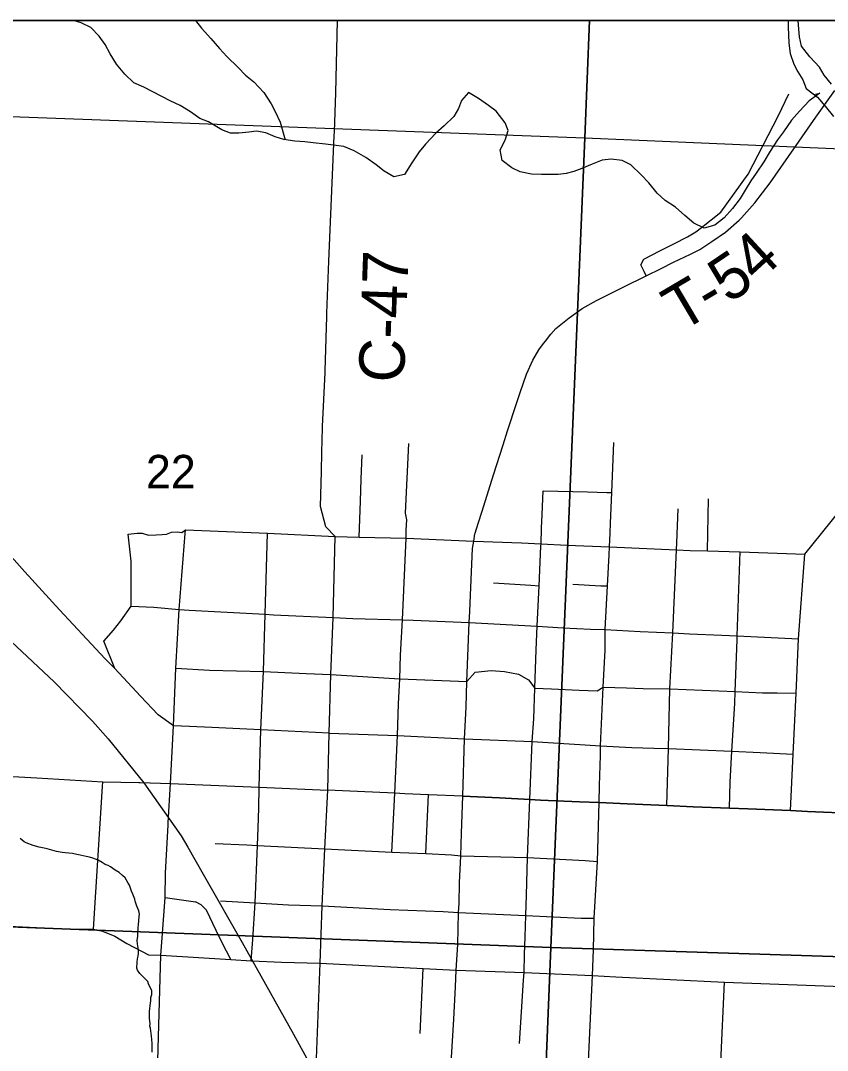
# Model space of a CAD drawing. Extents: x 0 to 34, y 0 to 22.
# Drawn here: x 3.4 to 4.408, y 19.613 to 20.9 of the extents above; entities that cross this region are included whole.
import ezdxf

# ---------------------------------------------------------------- set-up
doc = ezdxf.new("R2010")
doc.units = 0
for name, color, linetype in [('Default', 7, 'Continuous'), ('GM_X_City_Street', 7, 'Continuous'), ('GM_X_County_Road', 7, 'Continuous'), ('GM_X_County_Road_Text', 7, 'Continuous'), ('GM_X_Major_River', 7, 'Continuous'), ('GM_X_Minor_River', 7, 'Continuous'), ('GM_X_Rail_Line', 7, 'Continuous'), ('GM_X_Section', 7, 'Continuous'), ('GM_X_Section_Text', 7, 'Continuous'), ('GM_X_State_Route', 7, 'Continuous'), ('GM_X_Township_Road', 7, 'Continuous'), ('GM_X_Township_Road_Text', 7, 'Continuous'), ('GM_X_US_Route', 7, 'Continuous'), ('SH_Data', 7, 'Continuous')]:
    doc.layers.add(name, color=color, linetype=linetype)

msp = doc.modelspace()

# ---------------------------------------------------------------- linework, layer by layer
at = {"layer": 'Default'}
msp.add_lwpolyline([(6.0871, 20.9), (2.1, 20.9), (2.1, 17.8044), (2.8305, 17.7727), (2.976, 17.7664), (3.1037, 17.7609), (3.4544, 17.7458), (3.7662, 17.7368), (3.9904, 17.7296), (4.1165, 17.7286), (4.1238, 17.7269), (4.1354, 17.7264), (4.1969, 17.7246), (4.2769, 17.7222), (4.4203, 17.718), (4.506, 17.7155), (4.6237, 17.7121), (4.6735, 17.7102), (4.763, 17.7084), (4.9045, 17.7039), (4.98, 17.7015), (5.0396, 17.6997)], dxfattribs=at)
for points in [[(4.1106, 20.9), (3.1115, 20.9), (3.1076, 20.7906), (4.105, 20.7535)], [(5.1123, 20.9), (4.1106, 20.9), (4.105, 20.7535), (5.1049, 20.7104)]]:
    msp.add_lwpolyline(points, close=True, dxfattribs=at)
at = {"layer": 'GM_X_City_Street'}
for p, q in [((4.2579, 20.2373), (4.2594, 20.3024)), ((4.2196, 20.2471), (4.2216, 20.2897)), ((3.5806, 19.8039), (3.6183, 19.7988)), ((3.899, 19.6342), (3.9027, 19.7153)), ((4.0233, 19.6217), (4.0283, 19.7005))]:
    msp.add_line(p, q, dxfattribs=at)
for points in [[(3.8818, 20.2615), (3.8818, 20.2633), (3.8825, 20.276), (3.881, 20.2842), (3.8849, 20.3715)], [(4.1357, 20.2423), (4.1365, 20.2594), (4.137, 20.2717), (4.1385, 20.31), (4.1411, 20.3727)], [(3.8229, 20.2544), (3.8244, 20.2992), (3.8254, 20.327), (3.8268, 20.3574)], [(4.05, 20.2434), (4.0502, 20.2462), (4.0506, 20.2658), (4.0516, 20.2825), (4.0527, 20.3123)], [(4.0527, 20.3123), (4.1082, 20.3109), (4.1323, 20.31), (4.1385, 20.31)], [(3.5343, 20.2582), (3.5454, 20.2592), (3.5517, 20.2592), (3.5597, 20.257), (3.5692, 20.2571), (3.577, 20.2578), (3.5822, 20.2583), (3.5884, 20.2607), (3.5957, 20.2612), (3.6014, 20.2601), (3.6059, 20.2637)], [(3.5382, 20.1681), (3.5381, 20.2242), (3.5343, 20.2582)], [(3.5908, 20.0186), (3.594, 20.0907), (3.598, 20.1638), (3.6055, 20.2589), (3.6059, 20.2637)], [(3.6059, 20.2637), (3.7086, 20.2594), (3.7929, 20.2551), (3.8229, 20.2544), (3.8816, 20.2529), (3.9661, 20.2492)], [(3.6981, 19.9419), (3.7001, 20.0135), (3.7032, 20.0864), (3.7053, 20.1582), (3.7086, 20.2594)], [(3.8706, 20.0064), (3.8722, 20.0461), (3.8737, 20.0774), (3.8744, 20.107), (3.8772, 20.151), (3.8816, 20.2529), (3.8818, 20.2615)], [(3.9661, 20.2492), (4.0257, 20.2471), (4.0502, 20.2462), (4.0823, 20.2445), (4.1357, 20.2423), (4.2192, 20.2385), (4.2364, 20.2376), (4.2579, 20.2373), (4.2989, 20.236), (4.3798, 20.2329)], [(4.2074, 19.9191), (4.2093, 19.9904), (4.2112, 20.065), (4.2149, 20.1349), (4.2192, 20.2385), (4.2196, 20.2471)], [(4.0391, 19.9989), (4.0413, 20.0271), (4.0424, 20.0656), (4.044, 20.1137), (4.0452, 20.1432), (4.0479, 20.1934), (4.0494, 20.2329), (4.05, 20.2434)], [(4.1228, 19.9229), (4.1231, 19.9438), (4.1246, 19.9816), (4.1246, 19.9935), (4.1279, 20.067), (4.1301, 20.1131), (4.1303, 20.1391), (4.1332, 20.1934), (4.1353, 20.2321), (4.1357, 20.2423)], [(4.2855, 19.9157), (4.2866, 19.9483), (4.2884, 19.9869), (4.2922, 20.0465), (4.2926, 20.0614), (4.295, 20.1259), (4.2952, 20.1311), (4.2989, 20.236)], [(4.3619, 19.9126), (4.3652, 19.9832), (4.3688, 20.0595), (4.3719, 20.1273), (4.3798, 20.2329)], [(3.9908, 20.1971), (4.0375, 20.1945), (4.0479, 20.1934)], [(4.0897, 20.1955), (4.125, 20.1937), (4.1332, 20.1934)], [(3.5175, 20.0904), (3.5039, 20.1243), (3.5162, 20.138), (3.5252, 20.1497), (3.5382, 20.1681), (3.5663, 20.1667), (3.598, 20.1638), (3.6107, 20.1632), (3.7053, 20.1582), (3.7158, 20.1574), (3.7904, 20.1539), (3.8151, 20.1526), (3.8772, 20.151), (3.8905, 20.1505), (3.9604, 20.1476)], [(3.9604, 20.1476), (4.0452, 20.1432), (4.0777, 20.1411), (4.1118, 20.1394), (4.1303, 20.1391), (4.174, 20.1365), (4.2149, 20.1349), (4.2355, 20.1335), (4.2759, 20.1319), (4.2952, 20.1311), (4.3719, 20.1273)], [(3.594, 20.0907), (3.6358, 20.0883), (3.7032, 20.0864), (3.7565, 20.084), (3.7876, 20.0826), (3.8737, 20.0774), (3.9574, 20.0739)], [(3.9574, 20.0739), (3.9679, 20.0858), (3.9877, 20.0876), (4.0045, 20.0863), (4.0221, 20.0831), (4.0344, 20.0762), (4.0424, 20.0656), (4.0631, 20.0649), (4.0976, 20.063), (4.1202, 20.0624), (4.1279, 20.067), (4.1568, 20.066), (4.1777, 20.0653), (4.2112, 20.065), (4.2926, 20.0614), (4.3268, 20.06), (4.345, 20.0597), (4.3688, 20.0595)], [(4.0391, 19.9989), (4.1051, 19.9949), (4.1246, 19.9935), (4.1635, 19.9914), (4.1912, 19.9908), (4.2093, 19.9904), (4.2884, 19.9869), (4.3239, 19.9852), (4.3652, 19.9832)], [(3.491, 19.7643), (3.5024, 19.9426), (3.5026, 19.9485)], [(3.6881, 19.7247), (3.6899, 19.7515), (3.693, 19.7973), (3.6958, 19.8691), (3.6966, 19.8911), (3.6974, 19.9155), (3.6981, 19.9419)], [(3.9062, 19.8588), (3.9067, 19.8685), (3.9094, 19.9325)], [(4.1143, 19.7066), (4.1155, 19.7388), (4.1165, 19.778), (4.1208, 19.8492), (4.1228, 19.9229)], [(3.6431, 19.8714), (3.6824, 19.8699), (3.6958, 19.8691), (3.7801, 19.8649)], [(4.0283, 19.7005), (4.0289, 19.7104), (4.0296, 19.7329), (4.0302, 19.755), (4.0311, 19.7815), (4.0318, 19.8068), (4.0333, 19.854)], [(4.0333, 19.854), (4.1054, 19.8501), (4.1208, 19.8492)], [(3.6627, 19.7266), (3.6519, 19.7473), (3.6443, 19.7628), (3.6323, 19.7881), (3.6255, 19.7949), (3.6183, 19.7988)], [(3.6496, 19.7999), (3.693, 19.7973), (3.7347, 19.7947), (3.7767, 19.7936), (3.8618, 19.7891), (3.9277, 19.7865), (3.947, 19.7851)], [(3.947, 19.7851), (4.0311, 19.7815), (4.1004, 19.7781), (4.1165, 19.778)], [(3.5646, 19.1798), (3.5556, 19.2005), (3.5545, 19.2251), (3.5555, 19.2612), (3.5684, 19.4983), (3.5753, 19.7319)], [(4.0935, 19.2396), (4.0939, 19.2473), (4.0951, 19.2853), (4.095, 19.2916), (4.096, 19.3033), (4.0968, 19.3257), (4.0979, 19.3464), (4.0988, 19.3586), (4.0991, 19.3677), (4.099, 19.3763), (4.1143, 19.7066)], [(4.2554, 19.2326), (4.2569, 19.2528), (4.2701, 19.4982), (4.2795, 19.6982)]]:
    msp.add_lwpolyline(points, dxfattribs=at)
at = {"layer": 'GM_X_County_Road'}
for p, q in [((3.7762, 20.3606), (3.7772, 20.3906)), ((3.5753, 19.7319), (3.5769, 19.7535))]:
    msp.add_line(p, q, dxfattribs=at)
for points in [[(3.792, 20.7611), (3.7936, 20.8097), (3.7959, 20.9)], [(3.7825, 20.5302), (3.7826, 20.5342), (3.7851, 20.5995), (3.7918, 20.756), (3.792, 20.7611)], [(3.7803, 20.4601), (3.7804, 20.4621), (3.7825, 20.5302)], [(3.7772, 20.3906), (3.7773, 20.3926), (3.7803, 20.4601)], [(3.7929, 20.2551), (3.7814, 20.2673), (3.7748, 20.2926), (3.776, 20.3363), (3.7762, 20.3606)], [(3.7856, 20.0094), (3.7876, 20.0826), (3.7904, 20.1539), (3.7929, 20.2551)], [(2.7032, 20.1317), (2.7688, 20.0887), (2.8505, 20.0351), (2.9032, 20.0007), (2.921, 19.9928), (2.9306, 19.9898), (2.9591, 19.9866), (3.0508, 19.9729), (3.1096, 19.9678), (3.2187, 19.9627), (3.3527, 19.9573), (3.4202, 19.9534), (3.5026, 19.9485), (3.5475, 19.9479)], [(3.5843, 19.8948), (3.5844, 19.8974), (3.5871, 19.9465), (3.5908, 20.0186)], [(3.7856, 20.0094), (3.8706, 20.0064), (3.9545, 20.0022), (4.0391, 19.9989)], [(3.8637, 19.8607), (3.8675, 19.9343), (3.8706, 20.0064)], [(4.0333, 19.854), (4.0361, 19.9264), (4.0391, 19.9989)], [(3.5475, 19.9479), (3.5495, 19.9479), (3.5871, 19.9465)], [(3.5871, 19.9465), (3.6981, 19.9419), (3.7836, 19.9381)], [(3.774, 19.7218), (3.7767, 19.7936), (3.7801, 19.8649), (3.7836, 19.9381)], [(3.5769, 19.7535), (3.5806, 19.8039), (3.581, 19.8344), (3.5843, 19.8948)], [(3.7801, 19.8649), (3.8637, 19.8607), (3.9062, 19.8588), (3.9381, 19.8572), (3.95, 19.8562), (4.0333, 19.854)], [(2.7427, 19.7956), (2.8581, 19.789), (2.9159, 19.7881), (3.031, 19.7839), (3.2427, 19.773), (3.3579, 19.7693), (3.4112, 19.7668), (3.4626, 19.7644), (3.491, 19.7643), (3.5023, 19.762), (3.5178, 19.7556), (3.5325, 19.7466), (3.5599, 19.7323), (3.5753, 19.7319)], [(3.5753, 19.7319), (3.6627, 19.7266), (3.6881, 19.7247), (3.689, 19.7247)], [(3.689, 19.7247), (3.7258, 19.7231), (3.774, 19.7218), (3.9027, 19.7153), (3.9443, 19.7132)], [(3.7571, 19.254), (3.7606, 19.3413), (3.761, 19.3744), (3.7612, 19.3861), (3.774, 19.7218)], [(3.9443, 19.7132), (4.0289, 19.7104), (4.1143, 19.7066), (4.1437, 19.7048), (4.2795, 19.6982), (4.4492, 19.6919), (4.4711, 19.6913), (4.5591, 19.6887), (4.5735, 19.6877)]]:
    msp.add_lwpolyline(points, dxfattribs=at)
at = {"layer": 'GM_X_Major_River'}
for points in [[(4.3589, 20.9), (4.3587, 20.8916), (4.3592, 20.8821), (4.3596, 20.8719), (4.3612, 20.8589), (4.3661, 20.8455), (4.3708, 20.8359), (4.3773, 20.8258), (4.3812, 20.8151), (4.3957, 20.8041), (4.4049, 20.7932), (4.4155, 20.78)], [(4.4132, 20.8203), (4.4037, 20.8319), (4.3979, 20.8416), (4.3861, 20.8548), (4.3755, 20.868), (4.3731, 20.8795), (4.3723, 20.8894), (4.3715, 20.9)]]:
    msp.add_lwpolyline(points, dxfattribs=at)
at = {"layer": 'GM_X_Minor_River'}
for points in [[(3.5867, 20.7998), (3.5538, 20.8166), (3.5414, 20.8223), (3.5303, 20.8328), (3.5197, 20.8456), (3.512, 20.8583), (3.5055, 20.8702), (3.4982, 20.8806), (3.4875, 20.8915), (3.4755, 20.8971), (3.4659, 20.9)], [(3.6183, 20.9), (3.6261, 20.8906), (3.6375, 20.8774), (3.6486, 20.8649), (3.6574, 20.8552), (3.6718, 20.8415), (3.6811, 20.8318), (3.6915, 20.8235), (3.704, 20.8102), (3.7131, 20.7959), (3.7178, 20.7863), (3.7242, 20.7732), (3.7306, 20.7511)], [(4.3911, 20.8076), (4.3985, 20.8093), (4.3853, 20.7998), (4.3732, 20.7868), (4.363, 20.7757), (4.3531, 20.7608), (4.3456, 20.7508), (4.3365, 20.7366), (4.3285, 20.7235), (4.319, 20.7094), (4.3123, 20.6997), (4.3063, 20.69), (4.2987, 20.6777), (4.2893, 20.665), (4.2791, 20.6535), (4.2671, 20.6444), (4.254, 20.6406), (4.2409, 20.6466), (4.2298, 20.6564), (4.2183, 20.6666), (4.2053, 20.6753), (4.1953, 20.6843), (4.185, 20.6971), (4.1754, 20.7073), (4.1625, 20.7198), (4.1516, 20.725), (4.1376, 20.7269), (4.1266, 20.7257), (4.1139, 20.7207), (4.1012, 20.715), (4.0912, 20.7115), (4.0816, 20.7087), (4.0717, 20.7075), (4.0611, 20.7078), (4.0505, 20.7077), (4.0383, 20.708), (4.024, 20.7111), (4.0135, 20.7159), (4.0016, 20.725), (3.9989, 20.7383), (4.0054, 20.7507), (4.0091, 20.7627), (4.0052, 20.7723), (3.9942, 20.7867), (3.9845, 20.7938), (3.9719, 20.8028), (3.9595, 20.81), (3.9509, 20.8), (3.9472, 20.7902), (3.9412, 20.7802), (3.9291, 20.7683), (3.9186, 20.7591), (3.9057, 20.7455), (3.8979, 20.7358), (3.8887, 20.722), (3.8796, 20.7078), (3.8662, 20.7048), (3.8543, 20.7119), (3.8442, 20.7198), (3.8312, 20.7289), (3.8166, 20.7373), (3.8039, 20.7426), (3.791, 20.7441), (3.7808, 20.7455), (3.7653, 20.7471), (3.755, 20.7485), (3.7425, 20.7492), (3.7286, 20.7515), (3.718, 20.7548), (3.7064, 20.7597), (3.6947, 20.7619), (3.6851, 20.7607), (3.6726, 20.7591), (3.6623, 20.7594), (3.6514, 20.7635), (3.6346, 20.7734), (3.6237, 20.7775), (3.6122, 20.7858), (3.5991, 20.7938), (3.5867, 20.7998)], [(3.5626, 19.6749), (3.5628, 19.679), (3.5637, 19.6828), (3.5638, 19.6874), (3.5628, 19.6901), (3.561, 19.6932), (3.5599, 19.6963), (3.5589, 19.699), (3.5519, 19.7061), (3.5489, 19.7092), (3.546, 19.7131), (3.5453, 19.7158), (3.5456, 19.7231), (3.5461, 19.7272), (3.547, 19.7306), (3.5471, 19.7344), (3.5472, 19.7386), (3.5469, 19.7413), (3.546, 19.7459), (3.5457, 19.7501), (3.5463, 19.7558), (3.5464, 19.7588), (3.547, 19.7664), (3.5471, 19.7699), (3.5482, 19.7801), (3.5483, 19.7832), (3.5477, 19.7874), (3.5452, 19.7932), (3.5432, 19.7993), (3.5425, 19.802), (3.54, 19.8082), (3.5386, 19.8121), (3.5358, 19.8194), (3.5344, 19.8221), (3.5304, 19.8284), (3.5271, 19.8315), (3.523, 19.8351), (3.5181, 19.8383), (3.5122, 19.8423), (3.5092, 19.8439), (3.5058, 19.8452), (3.5017, 19.8476), (3.4968, 19.8505), (3.49, 19.853), (3.4859, 19.8543), (3.4817, 19.8552), (3.4745, 19.8569), (3.47, 19.8579), (3.4647, 19.8588), (3.4555, 19.8599), (3.4517, 19.8604), (3.4449, 19.8614), (3.4332, 19.8648), (3.4294, 19.8657), (3.423, 19.8671), (3.4158, 19.8689), (3.4071, 19.8722), (3.4045, 19.8735), (3.3993, 19.8778)], [(3.5643, 19.6108), (3.5645, 19.615), (3.5642, 19.6184), (3.5643, 19.6215), (3.5637, 19.6264), (3.5635, 19.6306), (3.5632, 19.6341), (3.5623, 19.6406), (3.5616, 19.6433), (3.5617, 19.6463), (3.5608, 19.6532), (3.5611, 19.662), (3.5616, 19.665), (3.5617, 19.6692), (3.5626, 19.6749)]]:
    msp.add_lwpolyline(points, dxfattribs=at)
at = {"layer": 'GM_X_Rail_Line'}
msp.add_lwpolyline([(2.5538, 20.9), (2.6699, 20.7921), (2.9476, 20.533), (3.1327, 20.3614), (3.2237, 20.277), (3.3405, 20.1683), (3.4419, 20.0737), (3.4898, 20.0243), (3.5092, 20.0023), (3.5538, 19.9473), (3.6006, 19.8809), (3.6088, 19.8671), (3.6176, 19.8515), (3.6298, 19.8303), (3.6768, 19.7476), (3.7408, 19.633), (3.7622, 19.5944), (3.79, 19.5454), (4.1053, 18.9832), (4.1141, 18.9644), (4.1259, 18.9412), (4.1333, 18.9272), (4.1473, 18.9034)], dxfattribs=at)
at = {"layer": 'GM_X_Section'}
for points in [[(3.1076, 20.7906), (4.105, 20.7535), (4.0623, 19.7415), (3.0692, 19.7796)], [(5.1049, 20.7104), (5.0674, 19.7096), (4.0623, 19.7415), (4.105, 20.7535)], [(3.0692, 19.7796), (4.0623, 19.7415), (4.0218, 18.7461), (3.0273, 18.7832)], [(4.0623, 19.7415), (5.0674, 19.7096), (5.0264, 18.7096), (4.0218, 18.7461)]]:
    msp.add_lwpolyline(points, close=True, dxfattribs=at)
at = {"layer": 'GM_X_State_Route'}
for points in [[(4.3005, 20.6534), (4.3174, 20.6721), (4.3362, 20.6971), (4.366, 20.7398), (4.3933, 20.7793), (4.4172, 20.8125)], [(4.0532, 20.4963), (4.0555, 20.4994), (4.0622, 20.5081), (4.0688, 20.5151), (4.0853, 20.5286), (4.1013, 20.5401), (4.1194, 20.55), (4.1534, 20.5672), (4.1815, 20.5809), (4.2, 20.5901), (4.2157, 20.5979), (4.2368, 20.608), (4.2486, 20.614), (4.2636, 20.6237), (4.2806, 20.6354), (4.2977, 20.6504), (4.3005, 20.6534)], [(4.0149, 20.4076), (4.024, 20.4352), (4.0318, 20.458), (4.0397, 20.4754), (4.0475, 20.4885), (4.0532, 20.4963)], [(3.9676, 20.2585), (3.9677, 20.2595), (3.9715, 20.2714), (3.9765, 20.2869), (3.9907, 20.3322), (4.0027, 20.3696), (4.0081, 20.3873), (4.0131, 20.4021), (4.0149, 20.4076)], [(3.9523, 19.9306), (3.9545, 20.0022), (3.9564, 20.0418), (3.9574, 20.0739), (3.9604, 20.1476), (3.961, 20.1615), (3.9619, 20.182), (3.9635, 20.2207), (3.9646, 20.2402), (3.9661, 20.2492), (3.9676, 20.2585)], [(3.9226, 19.2477), (3.9263, 19.3277), (3.9283, 19.3828), (3.9292, 19.4035), (3.9313, 19.4387), (3.9319, 19.4503), (3.9322, 19.466), (3.9339, 19.4922), (3.9349, 19.5231), (3.9376, 19.5907), (3.9384, 19.6041), (3.941, 19.652), (3.9432, 19.6924), (3.9443, 19.7132), (3.9462, 19.7451), (3.947, 19.7851), (3.9477, 19.7966), (3.9482, 19.8224), (3.95, 19.8562), (3.9506, 19.8844), (3.9523, 19.9306)], [(3.9523, 19.9306), (3.9983, 19.9285), (4.0361, 19.9264)], [(4.0361, 19.9264), (4.0496, 19.9256), (4.098, 19.9236), (4.1228, 19.9229)], [(4.1228, 19.9229), (4.1576, 19.921), (4.1873, 19.92), (4.2074, 19.9191)], [(4.2074, 19.9191), (4.24, 19.9173), (4.2855, 19.9157)], [(4.2855, 19.9157), (4.3084, 19.9148), (4.3619, 19.9126)], [(4.3619, 19.9126), (4.3832, 19.9114), (4.4436, 19.9092), (4.5147, 19.9063), (4.5817, 19.9046), (4.5816, 19.9036)]]:
    msp.add_lwpolyline(points, dxfattribs=at)
at = {"layer": 'GM_X_Township_Road'}
for points in [[(4.2506, 20.6414), (4.2747, 20.6605), (4.3088, 20.7081), (4.3463, 20.7807), (4.3596, 20.8083)], [(4.1815, 20.5809), (4.179, 20.5862), (4.1748, 20.5948), (4.1785, 20.602), (4.1986, 20.6123), (4.2159, 20.6209), (4.2332, 20.6296), (4.2437, 20.6359), (4.2506, 20.6414)], [(4.3798, 20.2329), (4.4228, 20.2867), (4.4363, 20.306), (4.4543, 20.3251), (4.4689, 20.3372), (4.4868, 20.35), (4.4979, 20.3592), (4.5054, 20.3674), (4.5261, 20.3977), (4.5326, 20.4057)]]:
    msp.add_lwpolyline(points, dxfattribs=at)
at = {"layer": 'GM_X_US_Route'}
msp.add_line((3.8022, 19.9373), (3.7836, 19.9381), dxfattribs=at)
for points in [[(3.6109, 20.0177), (3.5908, 20.0186), (3.5719, 20.0323), (3.5498, 20.0557), (3.5175, 20.0904), (3.5057, 20.1023), (3.4828, 20.127), (3.4484, 20.1637), (3.4051, 20.2112), (3.3749, 20.2451), (3.3427, 20.2852), (3.3299, 20.3005), (3.3099, 20.3263), (3.2816, 20.3609), (3.238, 20.4139), (3.2083, 20.4514), (3.1832, 20.4828), (3.1686, 20.5019), (3.137, 20.5404), (3.1178, 20.5639), (3.0859, 20.6036), (3.062, 20.6335), (3.0461, 20.6532)], [(3.7856, 20.0094), (3.7001, 20.0135), (3.6389, 20.0164), (3.6109, 20.0177)], [(3.7836, 19.9381), (3.7852, 19.9913), (3.7856, 20.0094)], [(3.9523, 19.9306), (3.9094, 19.9325), (3.8799, 19.9337), (3.8675, 19.9343), (3.8022, 19.9373)], [(4.0361, 19.9264), (3.9983, 19.9285), (3.9523, 19.9306)], [(4.1228, 19.9229), (4.098, 19.9236), (4.0496, 19.9256), (4.0361, 19.9264)], [(4.2074, 19.9191), (4.1873, 19.92), (4.1576, 19.921), (4.1228, 19.9229)], [(4.2855, 19.9157), (4.24, 19.9173), (4.2074, 19.9191)], [(4.3619, 19.9126), (4.3084, 19.9148), (4.2855, 19.9157)], [(4.5816, 19.9036), (4.5817, 19.9046), (4.5147, 19.9063), (4.4436, 19.9092), (4.3832, 19.9114), (4.3619, 19.9126)]]:
    msp.add_lwpolyline(points, dxfattribs=at)
at = {"layer": 'SH_Data'}
msp.add_line((2.1, 20.9), (8.9, 20.9), dxfattribs=at)

# ---------------------------------------------------------------- texts
at = {"layer": 'GM_X_County_Road_Text'}
msp.add_text('C-47', height=0.05682, rotation=87.9433, dxfattribs=at).set_placement((3.8789, 20.4469))
at = {"layer": 'GM_X_Section_Text'}
msp.add_text('22', height=0.04186, rotation=0, dxfattribs=at).set_placement((3.5565, 20.3153))
at = {"layer": 'GM_X_Township_Road_Text'}
for s, rotation, p in [('4', 42.6515, (4.3207, 20.5709)), ('5', 34.0428, (4.2844, 20.5455)), ('T', 30.5726, (4.2246, 20.51)), ('-', 30.7387, (4.2613, 20.5317))]:
    msp.add_text(s, height=0.0568, rotation=rotation, dxfattribs=at).set_placement(p)

doc.saveas('drawing.dxf')
